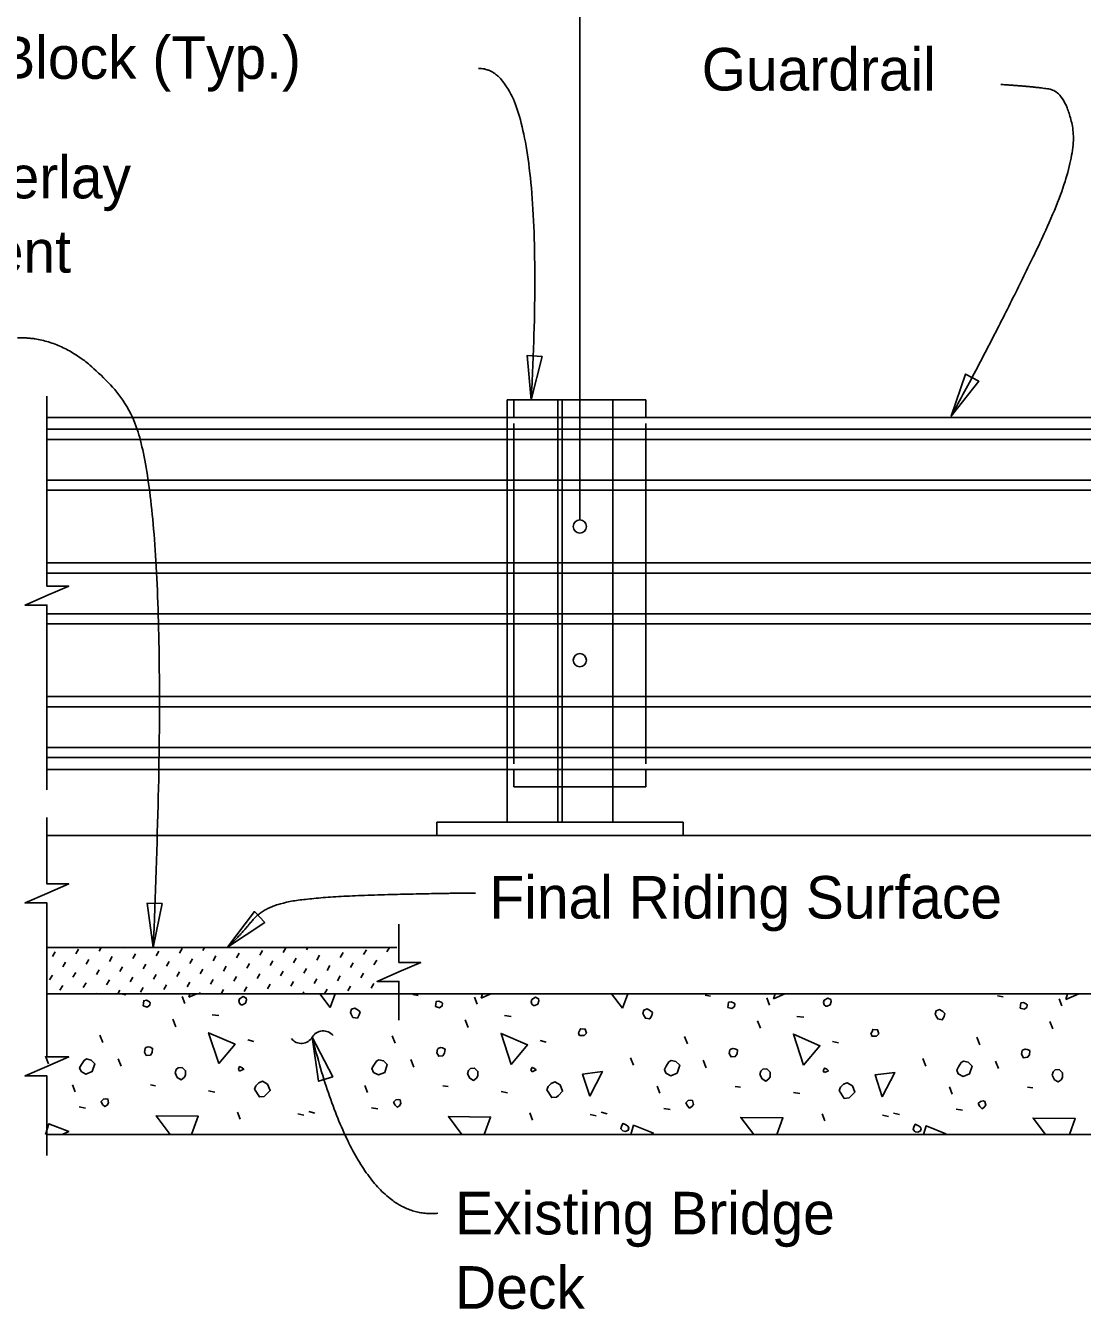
# Model space of a CAD drawing. Extents: x 21665 to 21741.5, y 56121.9 to 56164.2.
# Drawn here: x 21674.74 to 21679.75, y 56140.17 to 56146.25 of the extents above; entities that cross this region are included whole.
import ezdxf

# ---------------------------------------------------------------- set-up
doc = ezdxf.new("R2010")
doc.units = 0
for name, color, linetype in [('Dimension', 7, 'Continuous'), ('ExistSuperStruct', 7, 'Continuous'), ('Miscellaneous', 7, 'Continuous'), ('SteelMisc', 7, 'Continuous'), ('SteelMisc_h', 7, 'Continuous'), ('TextStructures', 7, 'Continuous')]:
    doc.layers.add(name, color=color, linetype=linetype)

msp = doc.modelspace()

# ---------------------------------------------------------------- linework, layer by layer
at = {"layer": 'Dimension'}
for points in [[(21677.1392, 56144.4808), (21677.1905, 56144.6857), (21677.1202, 56144.6912)], [(21679.1282, 56144.403), (21679.2583, 56144.5694), (21679.1962, 56144.603)], [(21675.348, 56141.8882), (21675.3203, 56142.0976), (21675.3908, 56142.0951)], [(21675.701, 56141.8885), (21675.8766, 56142.0059), (21675.8281, 56142.0572)], [(21676.1009, 56141.4629), (21676.1314, 56141.2539), (21676.1985, 56141.2756)]]:
    msp.add_lwpolyline(points, close=True, dxfattribs=at)
for points in [[(21674.8449, 56142.6344), (21674.8449, 56143.5089), (21674.7416, 56143.5089), (21674.8449, 56143.5539), (21674.9482, 56143.5989), (21674.8449, 56143.5989), (21674.8449, 56144.4978)], [(21674.8449, 56141.6686), (21674.8449, 56142.0985), (21674.7416, 56142.0985), (21674.8449, 56142.1435), (21674.9482, 56142.1885), (21674.8449, 56142.1885), (21674.8449, 56142.5035)], [(21676.5124, 56141.544), (21676.5124, 56141.7267), (21676.4091, 56141.7267), (21676.5124, 56141.7717), (21676.6158, 56141.8167), (21676.5124, 56141.8167), (21676.5124, 56141.9972)], [(21674.8449, 56140.9019), (21674.8449, 56141.2794), (21674.7416, 56141.2794), (21674.8449, 56141.3244), (21674.9482, 56141.3694), (21674.8449, 56141.3694), (21674.8449, 56141.6686)]]:
    msp.add_lwpolyline(points, dxfattribs=at)
for centre, start, end in [((21676.0501, 56141.4927), 218.26465, 329.99187), ((21676.1533, 56141.4331), 38.26465, 149.99187)]:
    msp.add_arc(centre, 0.0596, start, end, dxfattribs=at)
for points in [[(21677.1388, 56144.4811), (21677.2231, 56146.051), (21676.8886, 56146.051)], [(21679.3623, 56145.9744), (21679.5163, 56145.9651), (21679.6672, 56145.9405), (21679.735, 56145.62), (21679.3746, 56144.859), (21679.1282, 56144.4029)], [(21675.3488, 56141.8875), (21675.4466, 56144.1495), (21674.9833, 56144.7815), (21674.7064, 56144.7751)], [(21676.8754, 56142.145), (21676.7236, 56142.145), (21676.1497, 56142.1294), (21675.8759, 56142.0865), (21675.7604, 56141.9446), (21675.701, 56141.8885)], [(21676.1009, 56141.4629), (21676.3215, 56140.5891), (21676.697, 56140.6289)]]:
    msp.add_open_spline(points, degree=2, dxfattribs=at)
at = {"layer": 'ExistSuperStruct'}
for p, q in [((21674.8449, 56142.4186), (21684.442, 56142.4186)), ((21676.5028, 56141.8875), (21674.8448, 56141.8875)), ((21684.5591, 56141.6686), (21674.8449, 56141.6686)), ((21674.8449, 56141.0019), (21684.5591, 56141.0019))]:
    msp.add_line(p, q, dxfattribs=at)
at = {"layer": 'Miscellaneous'}
for p, q in [((21677.3691, 56150.2216), (21677.3691, 56143.9122)), ((21677.6816, 56144.4811), (21677.0566, 56144.4811)), ((21677.0566, 56144.4811), (21677.0566, 56144.3977)), ((21677.6816, 56144.4811), (21677.6816, 56144.3977)), ((21677.0566, 56144.3692), (21677.0566, 56142.7573)), ((21677.6816, 56144.3692), (21677.6816, 56142.7573)), ((21677.0566, 56142.6477), (21677.0566, 56142.7311)), ((21677.6816, 56142.6477), (21677.6816, 56142.7311)), ((21677.6816, 56142.6477), (21677.0566, 56142.6477)), ((21674.8709, 56141.8448), (21674.8838, 56141.8672)), ((21674.9815, 56141.8578), (21674.9945, 56141.8802)), ((21675.0921, 56141.8708), (21675.1018, 56141.8875)), ((21675.2028, 56141.8837), (21675.2049, 56141.8875)), ((21675.3622, 56141.8479), (21675.3752, 56141.8702)), ((21675.4729, 56141.8608), (21675.4858, 56141.8832)), ((21675.5835, 56141.8738), (21675.5914, 56141.8875)), ((21675.6941, 56141.8867), (21675.6946, 56141.8875)), ((21675.743, 56141.8379), (21675.7559, 56141.8603)), ((21675.8536, 56141.8509), (21675.8666, 56141.8733)), ((21675.9642, 56141.8638), (21675.9772, 56141.8862)), ((21676.0749, 56141.8768), (21676.081, 56141.8875)), ((21676.2343, 56141.8409), (21676.2473, 56141.8633)), ((21676.345, 56141.8539), (21676.3579, 56141.8763)), ((21676.4556, 56141.8669), (21676.4675, 56141.8875)), ((21674.9197, 56141.796), (21674.9327, 56141.8184)), ((21675.0303, 56141.809), (21675.0433, 56141.8314)), ((21675.141, 56141.8219), (21675.1539, 56141.8443)), ((21675.2516, 56141.8349), (21675.2646, 56141.8573)), ((21675.3004, 56141.7861), (21675.3134, 56141.8085)), ((21675.4111, 56141.799), (21675.424, 56141.8214)), ((21675.5217, 56141.812), (21675.5347, 56141.8344)), ((21675.6323, 56141.825), (21675.6453, 56141.8473)), ((21675.6812, 56141.7761), (21675.6941, 56141.7985)), ((21675.7918, 56141.7891), (21675.8048, 56141.8115)), ((21675.9024, 56141.802), (21675.9154, 56141.8244)), ((21676.0131, 56141.815), (21676.026, 56141.8374)), ((21676.1237, 56141.828), (21676.1367, 56141.8504)), ((21676.1725, 56141.7791), (21676.1855, 56141.8015)), ((21676.2832, 56141.7921), (21676.2961, 56141.8145)), ((21676.3938, 56141.8051), (21676.4068, 56141.8275)), ((21674.8579, 56141.7342), (21674.8709, 56141.7566)), ((21674.9685, 56141.7472), (21674.9815, 56141.7696)), ((21675.0792, 56141.7601), (21675.0921, 56141.7825)), ((21675.1898, 56141.7731), (21675.2028, 56141.7955)), ((21675.2386, 56141.7243), (21675.2516, 56141.7467)), ((21675.3493, 56141.7372), (21675.3622, 56141.7596)), ((21675.4599, 56141.7502), (21675.4729, 56141.7726)), ((21675.5705, 56141.7632), (21675.5835, 56141.7855)), ((21675.73, 56141.7273), (21675.743, 56141.7497)), ((21675.8406, 56141.7402), (21675.8536, 56141.7626)), ((21675.9513, 56141.7532), (21675.9642, 56141.7756)), ((21676.0619, 56141.7662), (21676.0749, 56141.7886)), ((21676.1107, 56141.7173), (21676.1237, 56141.7397)), ((21676.2214, 56141.7303), (21676.2343, 56141.7527)), ((21676.332, 56141.7433), (21676.345, 56141.7657)), ((21674.9067, 56141.6854), (21674.9197, 56141.7078)), ((21675.0174, 56141.6983), (21675.0303, 56141.7207)), ((21675.128, 56141.7113), (21675.141, 56141.7337)), ((21675.1804, 56141.6686), (21675.1898, 56141.6849)), ((21675.2875, 56141.6754), (21675.3004, 56141.6978)), ((21675.3981, 56141.6884), (21675.4111, 56141.7108)), ((21675.5087, 56141.7014), (21675.5217, 56141.7237)), ((21675.6194, 56141.7143), (21675.6323, 56141.7367)), ((21675.67, 56141.6686), (21675.6812, 56141.6879)), ((21675.7788, 56141.6784), (21675.7918, 56141.7008)), ((21675.8895, 56141.6914), (21675.9024, 56141.7138)), ((21676.0001, 56141.7044), (21676.0131, 56141.7268)), ((21676.0565, 56141.6686), (21676.0619, 56141.6779)), ((21676.1596, 56141.6686), (21676.1725, 56141.6909)), ((21676.2702, 56141.6815), (21676.2832, 56141.7039)), ((21676.3808, 56141.6944), (21676.3938, 56141.7168)), ((21675.0773, 56141.6686), (21675.0792, 56141.6719)), ((21675.1954, 56141.6686), (21675.2192, 56141.6638)), ((21675.4175, 56141.6686), (21675.4235, 56141.6674)), ((21675.4978, 56141.622), (21675.4855, 56141.6556)), ((21675.5669, 56141.6686), (21675.5705, 56141.6749)), ((21676.5773, 56141.6656), (21676.6038, 56141.6603)), ((21676.8825, 56141.6185), (21676.8701, 56141.6521)), ((21677.962, 56141.6621), (21677.9885, 56141.6568)), ((21678.2672, 56141.615), (21678.2548, 56141.6485)), ((21679.3467, 56141.6585), (21679.3732, 56141.6532)), ((21679.6519, 56141.6114), (21679.6395, 56141.645)), ((21675.628, 56141.5684), (21675.6599, 56141.5648)), ((21677.0127, 56141.5648), (21677.0445, 56141.5613)), ((21678.3974, 56141.5613), (21678.4292, 56141.5578)), ((21675.4554, 56141.5124), (21675.4413, 56141.5478)), ((21676.8401, 56141.5089), (21676.826, 56141.5443)), ((21678.2248, 56141.5054), (21678.2106, 56141.5407)), ((21679.6094, 56141.5018), (21679.5953, 56141.5372)), ((21675.1096, 56141.4376), (21675.0954, 56141.4729)), ((21675.796, 56141.4499), (21675.8243, 56141.4429)), ((21676.4942, 56141.434), (21676.4801, 56141.4694)), ((21677.1806, 56141.4464), (21677.2089, 56141.4393)), ((21677.8789, 56141.4305), (21677.8648, 56141.4658)), ((21678.5653, 56141.4429), (21678.5936, 56141.4358)), ((21679.2636, 56141.427), (21679.2495, 56141.4623)), ((21674.8532, 56141.3368), (21674.8391, 56141.3722)), ((21675.1973, 56141.325), (21675.1832, 56141.3604)), ((21676.582, 56141.3215), (21676.5679, 56141.3569)), ((21677.6226, 56141.3297), (21677.6084, 56141.3651)), ((21677.9667, 56141.318), (21677.9525, 56141.3533)), ((21679.0073, 56141.3262), (21678.9931, 56141.3615)), ((21679.3514, 56141.3144), (21679.3372, 56141.3498)), ((21674.9787, 56141.2042), (21674.9664, 56141.2378)), ((21675.3352, 56141.2367), (21675.36, 56141.2331)), ((21675.611, 56141.2084), (21675.641, 56141.2031)), ((21676.3634, 56141.2007), (21676.351, 56141.2343)), ((21676.7199, 56141.2331), (21676.7446, 56141.2296)), ((21676.9957, 56141.2048), (21677.0257, 56141.1995)), ((21677.7481, 56141.1971), (21677.7357, 56141.2307)), ((21678.1046, 56141.2296), (21678.1293, 56141.2261)), ((21678.3803, 56141.2013), (21678.4104, 56141.196)), ((21679.1328, 56141.1936), (21679.1204, 56141.2272)), ((21679.4892, 56141.2261), (21679.514, 56141.2225)), ((21674.9976, 56141.1324), (21675.0276, 56141.1271)), ((21675.7595, 56141.074), (21675.7471, 56141.1076)), ((21676.0335, 56141.1005), (21676.0618, 56141.0935)), ((21676.0859, 56141.1105), (21676.1142, 56141.1035)), ((21676.3822, 56141.1288), (21676.4123, 56141.1235)), ((21677.1442, 56141.0705), (21677.1318, 56141.1041)), ((21677.4182, 56141.097), (21677.4464, 56141.0899)), ((21677.4706, 56141.107), (21677.4988, 56141.0999)), ((21677.7669, 56141.1253), (21677.797, 56141.12)), ((21678.5288, 56141.067), (21678.5165, 56141.1005)), ((21678.8028, 56141.0935), (21678.8311, 56141.0864)), ((21678.8552, 56141.1035), (21678.8835, 56141.0964)), ((21679.1516, 56141.1218), (21679.1816, 56141.1165))]:
    msp.add_line(p, q, dxfattribs=at)
for points in [[(21675.3005, 56141.6108), (21675.3199, 56141.6055), (21675.3323, 56141.6143), (21675.3341, 56141.6267), (21675.3305, 56141.6302), (21675.3164, 56141.6373), (21675.304, 56141.6355), (21675.3022, 56141.6232), (21675.3005, 56141.6108)], [(21675.5167, 56141.6515), (21675.5219, 56141.6686)], [(21675.5548, 56141.6686), (21675.5167, 56141.6515)], [(21675.7642, 56141.6161), (21675.7712, 56141.6161), (21675.7854, 56141.6232), (21675.7907, 56141.6391), (21675.7889, 56141.6479), (21675.7748, 56141.655), (21675.7571, 56141.6444), (21675.7535, 56141.6338), (21675.7571, 56141.6232), (21675.7642, 56141.6161)], [(21676.1866, 56141.6037), (21676.1374, 56141.6686)], [(21676.2109, 56141.6686), (21676.1866, 56141.6037)], [(21676.6852, 56141.6073), (21676.7046, 56141.602), (21676.717, 56141.6108), (21676.7187, 56141.6232), (21676.7152, 56141.6267), (21676.7011, 56141.6338), (21676.6887, 56141.632), (21676.6869, 56141.6196), (21676.6852, 56141.6073)], [(21676.9013, 56141.6479), (21676.9077, 56141.6686)], [(21676.9473, 56141.6686), (21676.9013, 56141.6479)], [(21677.1488, 56141.6126), (21677.1559, 56141.6126), (21677.17, 56141.6196), (21677.1753, 56141.6355), (21677.1736, 56141.6444), (21677.1594, 56141.6515), (21677.1418, 56141.6409), (21677.1382, 56141.6302), (21677.1418, 56141.6196), (21677.1488, 56141.6126)], [(21677.5713, 56141.6002), (21677.5193, 56141.6686)], [(21677.5969, 56141.6686), (21677.5713, 56141.6002)], [(21678.0698, 56141.6037), (21678.0893, 56141.5984), (21678.1017, 56141.6073), (21678.1034, 56141.6196), (21678.0999, 56141.6232), (21678.0857, 56141.6302), (21678.0734, 56141.6285), (21678.0716, 56141.6161), (21678.0698, 56141.6037)], [(21678.286, 56141.6444), (21678.2935, 56141.6686)], [(21678.3399, 56141.6686), (21678.286, 56141.6444)], [(21678.5335, 56141.609), (21678.5406, 56141.609), (21678.5547, 56141.6161), (21678.56, 56141.632), (21678.5583, 56141.6409), (21678.5441, 56141.6479), (21678.5264, 56141.6373), (21678.5229, 56141.6267), (21678.5264, 56141.6161), (21678.5335, 56141.609)], [(21679.4545, 56141.6002), (21679.474, 56141.5949), (21679.4863, 56141.6037), (21679.4881, 56141.6161), (21679.4846, 56141.6196), (21679.4704, 56141.6267), (21679.458, 56141.6249), (21679.4563, 56141.6126), (21679.4545, 56141.6002)], [(21679.6707, 56141.6409), (21679.6792, 56141.6686)], [(21679.7324, 56141.6686), (21679.6707, 56141.6409)], [(21676.2856, 56141.5719), (21676.2945, 56141.556), (21676.3157, 56141.5525), (21676.3245, 56141.5684), (21676.3281, 56141.5825), (21676.3192, 56141.5914), (21676.3033, 56141.6002), (21676.2874, 56141.5949), (21676.2821, 56141.579), (21676.2856, 56141.5719)], [(21677.6703, 56141.5684), (21677.6792, 56141.5525), (21677.7004, 56141.5489), (21677.7092, 56141.5648), (21677.7127, 56141.579), (21677.7039, 56141.5878), (21677.688, 56141.5967), (21677.6721, 56141.5914), (21677.6668, 56141.5754), (21677.6703, 56141.5684)], [(21679.055, 56141.5648), (21679.0638, 56141.5489), (21679.085, 56141.5454), (21679.0939, 56141.5613), (21679.0974, 56141.5754), (21679.0886, 56141.5843), (21679.0727, 56141.5931), (21679.0568, 56141.5878), (21679.0515, 56141.5719), (21679.055, 56141.5648)], [(21677.368, 56141.4711), (21677.3892, 56141.4711), (21677.3999, 56141.4818), (21677.3945, 56141.5012), (21677.3716, 56141.503), (21677.368, 56141.4924), (21677.3627, 56141.4835), (21677.368, 56141.4711), (21677.3645, 56141.4747)], [(21678.7527, 56141.4676), (21678.7739, 56141.4676), (21678.7845, 56141.4782), (21678.7792, 56141.4977), (21678.7562, 56141.4994), (21678.7527, 56141.4888), (21678.7474, 56141.48), (21678.7527, 56141.4676), (21678.7492, 56141.4711)], [(21675.6587, 56141.3374), (21675.611, 56141.4841), (21675.7365, 56141.4293), (21675.6587, 56141.3374)], [(21677.0434, 56141.3339), (21676.9957, 56141.4806), (21677.1212, 56141.4258), (21677.0434, 56141.3339)], [(21678.4281, 56141.3304), (21678.3803, 56141.4771), (21678.5058, 56141.4223), (21678.4281, 56141.3304)], [(21675.3069, 56141.3922), (21675.3158, 56141.3763), (21675.3352, 56141.3781), (21675.344, 56141.3905), (21675.3458, 56141.4099), (21675.3334, 56141.4152), (21675.3246, 56141.417), (21675.314, 56141.4134), (21675.3105, 56141.4099), (21675.3069, 56141.3922)], [(21676.6916, 56141.3887), (21676.7004, 56141.3728), (21676.7199, 56141.3745), (21676.7287, 56141.3869), (21676.7305, 56141.4064), (21676.7181, 56141.4117), (21676.7093, 56141.4134), (21676.6987, 56141.4099), (21676.6951, 56141.4064), (21676.6916, 56141.3887)], [(21678.0763, 56141.3852), (21678.0851, 56141.3692), (21678.1046, 56141.371), (21678.1134, 56141.3834), (21678.1152, 56141.4028), (21678.1028, 56141.4081), (21678.094, 56141.4099), (21678.0834, 56141.4064), (21678.0798, 56141.4028), (21678.0763, 56141.3852)], [(21679.461, 56141.3816), (21679.4698, 56141.3657), (21679.4892, 56141.3675), (21679.4981, 56141.3798), (21679.4998, 56141.3993), (21679.4875, 56141.4046), (21679.4786, 56141.4064), (21679.468, 56141.4028), (21679.4645, 56141.3993), (21679.461, 56141.3816)], [(21675.007, 56141.2997), (21675.03, 56141.2873), (21675.0601, 56141.2997), (21675.0724, 56141.3368), (21675.0548, 56141.3545), (21675.0318, 56141.3598), (21675.0212, 56141.3527), (21675.0088, 56141.3333), (21675, 56141.3174), (21675.007, 56141.2997)], [(21675.4519, 56141.2932), (21675.4625, 56141.272), (21675.4802, 56141.2614), (21675.4943, 56141.272), (21675.5014, 56141.2826), (21675.5014, 56141.3038), (21675.4855, 56141.3197), (21675.466, 56141.318), (21675.4572, 56141.3091), (21675.4519, 56141.2932)], [(21675.7577, 56141.3021), (21675.7772, 56141.3109), (21675.7701, 56141.318), (21675.7577, 56141.3233), (21675.7524, 56141.3109), (21675.7577, 56141.3021)], [(21676.3917, 56141.2961), (21676.4147, 56141.2838), (21676.4447, 56141.2961), (21676.4571, 56141.3333), (21676.4394, 56141.3509), (21676.4165, 56141.3562), (21676.4059, 56141.3492), (21676.3935, 56141.3297), (21676.3846, 56141.3138), (21676.3917, 56141.2961)], [(21676.8366, 56141.2897), (21676.8472, 56141.2685), (21676.8648, 56141.2579), (21676.879, 56141.2685), (21676.8861, 56141.2791), (21676.8861, 56141.3003), (21676.8701, 56141.3162), (21676.8507, 56141.3144), (21676.8419, 56141.3056), (21676.8366, 56141.2897)], [(21677.1424, 56141.2985), (21677.1618, 56141.3074), (21677.1548, 56141.3144), (21677.1424, 56141.3197), (21677.1371, 56141.3074), (21677.1424, 56141.2985)], [(21677.7764, 56141.2926), (21677.7994, 56141.2802), (21677.8294, 56141.2926), (21677.8418, 56141.3297), (21677.8241, 56141.3474), (21677.8011, 56141.3527), (21677.7905, 56141.3456), (21677.7782, 56141.3262), (21677.7693, 56141.3103), (21677.7764, 56141.2926)], [(21678.2212, 56141.2862), (21678.2318, 56141.2649), (21678.2495, 56141.2543), (21678.2637, 56141.2649), (21678.2707, 56141.2755), (21678.2707, 56141.2968), (21678.2548, 56141.3127), (21678.2354, 56141.3109), (21678.2265, 56141.3021), (21678.2212, 56141.2862)], [(21678.5271, 56141.295), (21678.5465, 56141.3038), (21678.5394, 56141.3109), (21678.5271, 56141.3162), (21678.5218, 56141.3038), (21678.5271, 56141.295)], [(21679.1611, 56141.2891), (21679.184, 56141.2767), (21679.2141, 56141.2891), (21679.2265, 56141.3262), (21679.2088, 56141.3439), (21679.1858, 56141.3492), (21679.1752, 56141.3421), (21679.1628, 56141.3227), (21679.154, 56141.3067), (21679.1611, 56141.2891)], [(21675.8284, 56141.2172), (21675.8514, 56141.1801), (21675.8744, 56141.1819), (21675.8832, 56141.1907), (21675.9027, 56141.2101), (21675.8903, 56141.2402), (21675.8655, 56141.2543), (21675.8479, 56141.2473), (21675.8337, 56141.2331), (21675.8284, 56141.2172)], [(21677.2131, 56141.2137), (21677.2361, 56141.1766), (21677.2591, 56141.1783), (21677.2679, 56141.1872), (21677.2873, 56141.2066), (21677.275, 56141.2367), (21677.2502, 56141.2508), (21677.2325, 56141.2437), (21677.2184, 56141.2296), (21677.2131, 56141.2137)], [(21677.4158, 56141.183), (21677.3822, 56141.2873), (21677.4759, 56141.2997), (21677.4158, 56141.183)], [(21678.8004, 56141.1795), (21678.7669, 56141.2838), (21678.8605, 56141.2961), (21678.8004, 56141.1795)], [(21679.6059, 56141.2826), (21679.6165, 56141.2614), (21679.6342, 56141.2508), (21679.6483, 56141.2614), (21679.6554, 56141.272), (21679.6554, 56141.2932), (21679.6395, 56141.3091), (21679.6201, 56141.3074), (21679.6112, 56141.2985), (21679.6059, 56141.2826)], [(21678.5978, 56141.2101), (21678.6208, 56141.173), (21678.6437, 56141.1748), (21678.6526, 56141.1836), (21678.672, 56141.2031), (21678.6596, 56141.2331), (21678.6349, 56141.2473), (21678.6172, 56141.2402), (21678.6031, 56141.2261), (21678.5978, 56141.2101)], [(21675.1089, 56141.1447), (21675.1195, 56141.1341), (21675.1301, 56141.1412), (21675.1372, 56141.1518), (21675.1337, 56141.1695), (21675.1248, 56141.1713), (21675.1125, 56141.1695), (21675.1019, 56141.1589), (21675.1089, 56141.1447)], [(21676.4936, 56141.1412), (21676.5042, 56141.1306), (21676.5148, 56141.1377), (21676.5219, 56141.1483), (21676.5184, 56141.1659), (21676.5095, 56141.1677), (21676.4971, 56141.1659), (21676.4865, 56141.1553), (21676.4936, 56141.1412)], [(21677.8783, 56141.1377), (21677.8889, 56141.1271), (21677.8995, 56141.1341), (21677.9066, 56141.1447), (21677.903, 56141.1624), (21677.8942, 56141.1642), (21677.8818, 56141.1624), (21677.8712, 56141.1518), (21677.8783, 56141.1377)], [(21679.263, 56141.1341), (21679.2736, 56141.1235), (21679.2842, 56141.1306), (21679.2913, 56141.1412), (21679.2877, 56141.1589), (21679.2789, 56141.1606), (21679.2665, 56141.1589), (21679.2559, 56141.1483), (21679.263, 56141.1341)], [(21675.4286, 56141.0019), (21675.3617, 56141.0899), (21675.5615, 56141.0882), (21675.5292, 56141.0019)], [(21676.8106, 56141.0019), (21676.7464, 56141.0864), (21676.9462, 56141.0846), (21676.9152, 56141.0019)], [(21678.1926, 56141.0019), (21678.1311, 56141.0829), (21678.3308, 56141.0811), (21678.3012, 56141.0019)], [(21679.5746, 56141.0019), (21679.5158, 56141.0793), (21679.7155, 56141.0776), (21679.6872, 56141.0019)], [(21674.8387, 56141.0019), (21674.8544, 56141.0528), (21674.9481, 56141.0157), (21674.9174, 56141.0019)], [(21677.5731, 56141.0186), (21677.5855, 56141.0168), (21677.5978, 56141.0221), (21677.6014, 56141.0327), (21677.5961, 56141.0416), (21677.5855, 56141.0486), (21677.5731, 56141.054), (21677.566, 56141.0398), (21677.5625, 56141.0292), (21677.5731, 56141.0186)], [(21677.6102, 56141.0019), (21677.6237, 56141.0457), (21677.7174, 56141.0086), (21677.7025, 56141.0019)], [(21678.9578, 56141.0151), (21678.9701, 56141.0133), (21678.9825, 56141.0186), (21678.9861, 56141.0292), (21678.9808, 56141.038), (21678.9701, 56141.0451), (21678.9578, 56141.0504), (21678.9507, 56141.0363), (21678.9472, 56141.0257), (21678.9578, 56141.0151)], [(21678.996, 56141.0019), (21679.0084, 56141.0422), (21679.1021, 56141.0051), (21679.095, 56141.0019)]]:
    msp.add_lwpolyline(points, dxfattribs=at)
at = {"layer": 'SteelMisc'}
for p, q in [((21677.0254, 56144.4811), (21677.5254, 56144.4811)), ((21677.0254, 56144.4811), (21677.0254, 56144.3977)), ((21677.5254, 56144.4811), (21677.5254, 56144.3977)), ((21683.1087, 56144.3977), (21674.8449, 56144.3977)), ((21674.8449, 56144.3422), (21683.1087, 56144.3422)), ((21674.8449, 56144.294), (21683.1087, 56144.294)), ((21674.8449, 56144.1012), (21683.1087, 56144.1012)), ((21674.8449, 56144.053), (21683.1087, 56144.053)), ((21674.8449, 56143.709), (21683.1087, 56143.709)), ((21674.8449, 56143.6608), (21683.1087, 56143.6608)), ((21674.8449, 56143.468), (21683.1087, 56143.468)), ((21674.8449, 56143.4198), (21683.1087, 56143.4198)), ((21674.8449, 56143.0759), (21683.1087, 56143.0759)), ((21674.8449, 56143.0276), (21683.1087, 56143.0276)), ((21674.8449, 56142.8348), (21683.1087, 56142.8348)), ((21674.8449, 56142.7866), (21683.1087, 56142.7866)), ((21683.1087, 56142.7311), (21674.8449, 56142.7311)), ((21677.0254, 56142.7311), (21677.0254, 56142.4811)), ((21677.5254, 56142.7311), (21677.5254, 56142.4811)), ((21676.692, 56142.4811), (21677.8587, 56142.4811)), ((21676.692, 56142.4186), (21676.692, 56142.4811)), ((21677.0254, 56142.4811), (21677.5254, 56142.4811)), ((21677.8587, 56142.4811), (21677.8587, 56142.4186)), ((21676.692, 56142.4186), (21677.8587, 56142.4186))]:
    msp.add_line(p, q, dxfattribs=at)
for centre in [(21677.3691, 56143.881), (21677.3691, 56143.2479)]:
    msp.add_circle(centre, 0.0312, dxfattribs=at)
at = {"layer": 'SteelMisc_h'}
for p, q in [((21677.265, 56142.4811), (21677.265, 56144.4811)), ((21677.2858, 56142.4811), (21677.2858, 56144.4811)), ((21677.0254, 56144.3977), (21677.0254, 56142.7311)), ((21677.5254, 56144.3977), (21677.5254, 56142.7311))]:
    msp.add_line(p, q, dxfattribs=at)

# ---------------------------------------------------------------- texts
at = {"layer": 'Dimension'}
for s, p in [('Offset Block (Typ.)', (21673.8161, 56146.0013)), ('Guardrail', (21677.9463, 56145.9458)), ('Asphalt Overlay', (21673.3405, 56145.4353)), ('when present', (21673.3405, 56145.0833)), ('Existing Bridge', (21676.7783, 56140.5288)), ('Deck', (21676.7783, 56140.1768))]:
    msp.add_text(s, height=0.2016, dxfattribs=at).set_placement(p)
at = {"layer": 'TextStructures'}
msp.add_text('Final Riding Surface', height=0.2016, dxfattribs=at).set_placement((21676.941, 56142.0245))

doc.saveas('drawing.dxf')
